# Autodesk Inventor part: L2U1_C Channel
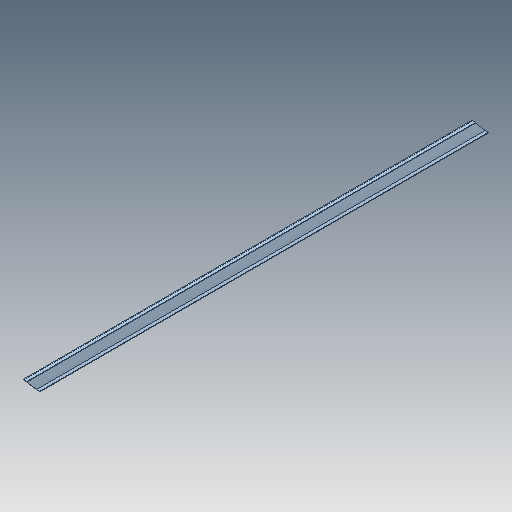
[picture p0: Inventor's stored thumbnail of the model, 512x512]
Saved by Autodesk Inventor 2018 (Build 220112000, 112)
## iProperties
Created: 2018-02
Part Number: L2U1_C Channel
Material: Steel, Mild
Document SubType Name: Modeling
Designer: STK
Density: 7.85 g/cm^3
Appearance: Light Steel Blue
Author: STK
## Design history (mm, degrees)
sketch "Sketch1"
  geometry: L1 (12.7, 177.8)-(12.7, -177.8); L2 (0, -190.5)-(0, 190.5); L3 (0, -190.5)-(92.075, -190.5); L4 (92.075, -190.5)-(92.075, -177.8); L5 (92.075, -177.8)-(12.7, -177.8); L6 (0, 190.5)-(92.075, 190.5); L7 (92.075, 190.5)-(92.075, 177.8); L8 (92.075, 177.8)-(12.7, 177.8); L9 (0, 0)-(92.075, 0)
  constraints: 18 end point, 3 horizontal, 3 parallel, 2 perpendicular, 2 vertical alignment, 1 collinear, 1 point on line, 1 vertical, 1 other
  dimensions: "d0" = 381 distance of L2.start L2.end; "d1" = 12.7 distance between parallel lines of L2 L1; "d2" = 92.075 distance of L2.end L6.end; "d3" = 12.7 distance between parallel lines of L3 L5
extrude "Extrusion1" new body sketch "Sketch1" stored distance "d4" = 11379.2; taper "d5" = 0 deg
sketch "Sketch2"
  geometry: L1 (-6273.832, 5940.973)-(-11379.2, 0) reference; L2 (-11379.2, 381)-(0, 381) reference; L3 (-11379.2, 0)-(-11379.2, 381) reference; L4 (-11379.2, 0)-(-11051.788, 381); L5 (-11379.2, 381)-(-11051.788, 381); L6 (-11379.2, 381)-(0, 381) reference; L7 (-11379.2, 381)-(-11379.2, 0); L8 (-11379.2, 368.3)-(0, 368.3) reference; L9 (83.322, 477.96)-(-5022.046, -5463.013) reference; L10 (0, 0)-(-11379.2, 0) reference; L11 (0, 0)-(-327.412, 0); L12 (0, 368.3)-(0, 381) reference; L13 (0, 381)-(-327.412, 0); L14 (0, 0)-(0, 381); 1 further point
  constraints: 12 end point, 2 point on line, 1 perpendicular, 1 vertical
extrude "Extrusion2" cut sketch "Sketch2" extent not by distance; stored distance "d6" = 11811; taper "d7" = 0 deg
sketch "Sketch3"
  geometry: L1 (83.322, 477.96)-(-5022.046, -5463.013) reference; L2 (0, 381)-(0, 0) reference; L3 (0, 0)-(-11379.2, 0) reference; L4 (-11051.788, 381)-(0, 381) reference; L5 (0, 381)-(0, 0); L6 (-11379.2, 0)-(0, 0) reference; L7 (-327.412, 0)-(0, 381); 1 further point
  constraints: 4 end point, 2 collinear, 2 point on line
extrude "Extrusion3" cut sketch "Sketch3" extent not by distance; stored distance "d8" = 11811; taper "d9" = 0 deg
body "Solid1"
node "Reference1"
node "Reference2"
node "Reference3"
